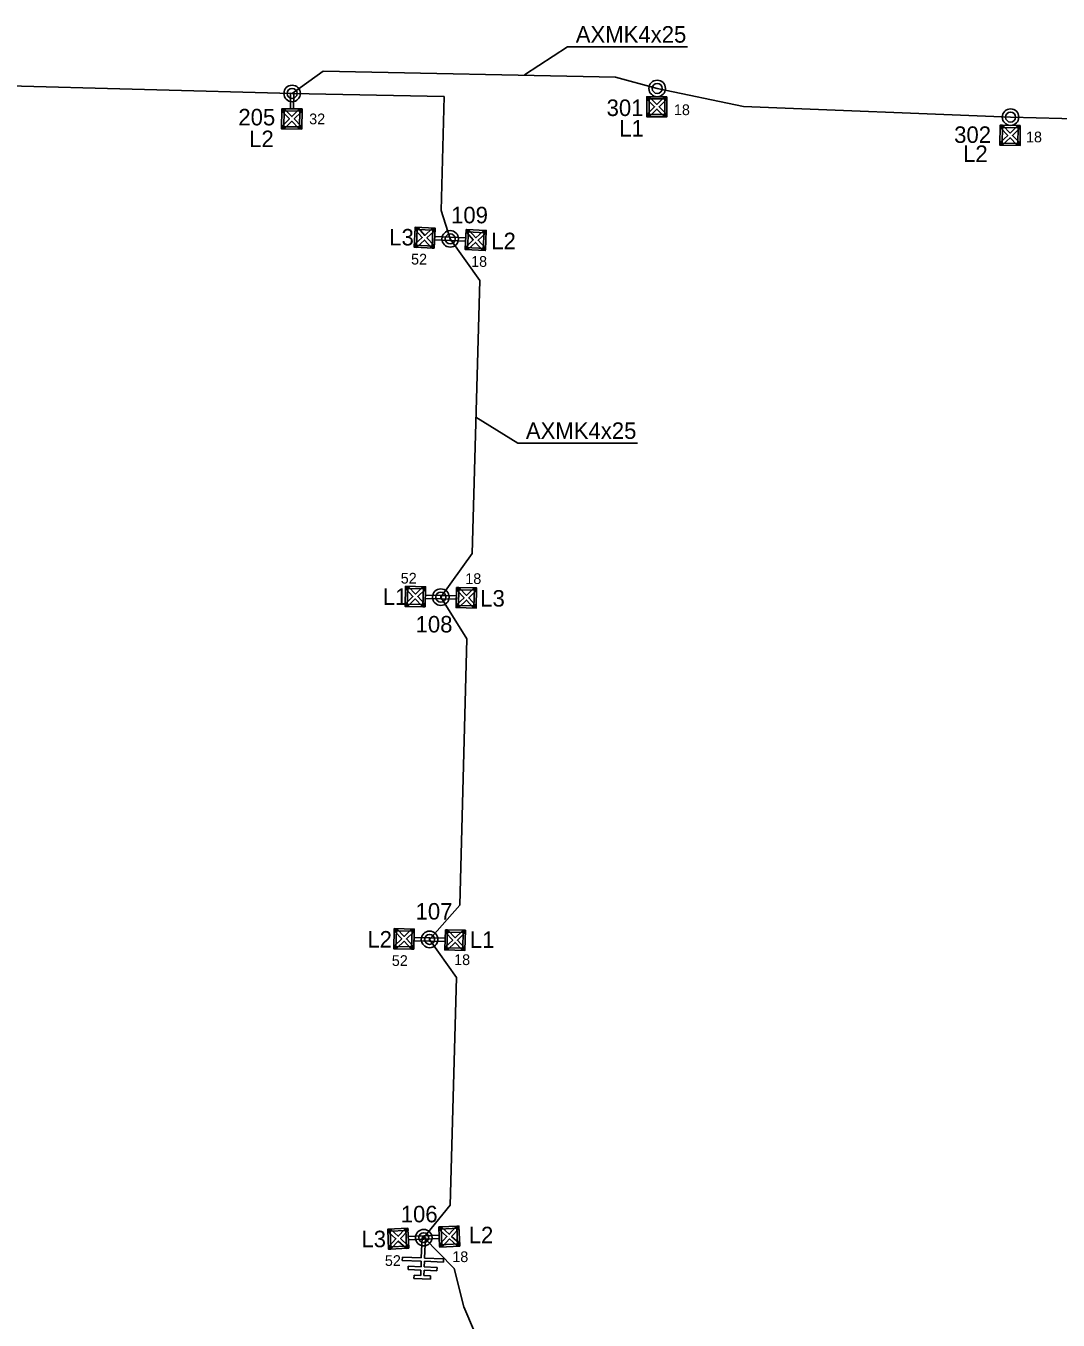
# Model space of a CAD drawing. Extents: x 25497852 to 25498297, y 6686544 to 6687252.
# Drawn here: x 25498074.6 to 25498168.3, y 6687062.7 to 6687180.2 of the extents above; entities that cross this region are included whole.
import ezdxf

# ---------------------------------------------------------------- set-up
doc = ezdxf.new("R2010")
doc.units = 0
for name, color, linetype in [('KayttoOikeusYksikko_piste_tunnus', 7, 'Continuous'), ('KiinteistoNimi', 7, 'Continuous'), ('Rajamerkki_tonttipyykki', 7, 'Continuous'), ('Rasitealue', 7, 'Continuous'), ('Rasiteviiva', 7, 'Continuous'), ('Taso 1', 7, 'Continuous')]:
    doc.layers.add(name, color=color, linetype=linetype)

msp = doc.modelspace()

# ---------------------------------------------------------------- linework, layer by layer
at = {"layer": 'KayttoOikeusYksikko_piste_tunnus'}
for points in [[(25498098.89, 6687174.02), (25498098.88, 6687172.62), (25498098.58, 6687172.62), (25498098.59, 6687174.03)], [(25498131.14, 6687173.72), (25498131.14, 6687171.9), (25498130.94, 6687171.9), (25498130.94, 6687173.72)], [(25498132.76, 6687173.72), (25498132.76, 6687173.52), (25498131, 6687173.52), (25498131, 6687173.72)], [(25498131.21, 6687173.66), (25498131.85, 6687173.02), (25498132.49, 6687173.66), (25498132.7, 6687173.66), (25498132.7, 6687173.45), (25498132.06, 6687172.81), (25498132.7, 6687172.17), (25498132.7, 6687171.96), (25498132.49, 6687171.96), (25498131.85, 6687172.6), (25498131.21, 6687171.96), (25498131, 6687171.96), (25498131, 6687172.17), (25498131.64, 6687172.81), (25498131, 6687173.45), (25498131, 6687173.66)], [(25498132.76, 6687171.96), (25498132.76, 6687173.66), (25498132.56, 6687173.66), (25498132.56, 6687171.96)], [(25498098.01, 6687172.63), (25498097.99, 6687170.8), (25498097.79, 6687170.8), (25498097.81, 6687172.63)], [(25498098.09, 6687172.56), (25498098.72, 6687171.92), (25498099.36, 6687172.55), (25498099.58, 6687172.55), (25498099.57, 6687172.33), (25498098.93, 6687171.7), (25498099.56, 6687171.06), (25498099.56, 6687170.85), (25498099.35, 6687170.85), (25498098.71, 6687171.49), (25498098.07, 6687170.86), (25498097.85, 6687170.87), (25498097.86, 6687171.08), (25498098.5, 6687171.71), (25498097.87, 6687172.35), (25498097.87, 6687172.57)], [(25498099.64, 6687172.61), (25498099.64, 6687172.41), (25498097.87, 6687172.43), (25498097.87, 6687172.63)], [(25498099.62, 6687170.85), (25498099.64, 6687172.55), (25498099.44, 6687172.55), (25498099.42, 6687170.85)], [(25498097.86, 6687171), (25498097.85, 6687170.8), (25498099.62, 6687170.78), (25498099.62, 6687170.98)], [(25498131, 6687172.1), (25498131, 6687171.9), (25498132.76, 6687171.9), (25498132.76, 6687172.1)], [(25498163.22, 6687171.13), (25498163.19, 6687169.31), (25498162.99, 6687169.31), (25498163.02, 6687171.14)], [(25498163.29, 6687171.07), (25498163.92, 6687170.42), (25498164.57, 6687171.05), (25498164.78, 6687171.05), (25498164.78, 6687170.84), (25498164.13, 6687170.21), (25498164.76, 6687169.56), (25498164.76, 6687169.35), (25498164.54, 6687169.35), (25498163.91, 6687170), (25498163.27, 6687169.37), (25498163.05, 6687169.37), (25498163.06, 6687169.59), (25498163.71, 6687170.21), (25498163.08, 6687170.86), (25498163.08, 6687171.07)], [(25498164.84, 6687171.11), (25498164.84, 6687170.91), (25498163.08, 6687170.94), (25498163.08, 6687171.14)], [(25498164.82, 6687169.35), (25498164.84, 6687171.05), (25498164.64, 6687171.05), (25498164.62, 6687169.35)], [(25498163.06, 6687169.51), (25498163.05, 6687169.31), (25498164.82, 6687169.29), (25498164.82, 6687169.49)], [(25498110.1, 6687161.81), (25498109.9, 6687161.82), (25498109.82, 6687160.06), (25498110.02, 6687160.05)], [(25498111.65, 6687161.53), (25498110.98, 6687160.92), (25498111.59, 6687160.25), (25498111.58, 6687160.04), (25498111.37, 6687160.05), (25498110.76, 6687160.71), (25498110.09, 6687160.11), (25498109.88, 6687160.12), (25498109.89, 6687160.33), (25498110.56, 6687160.94), (25498109.95, 6687161.61), (25498109.96, 6687161.82), (25498110.17, 6687161.81), (25498110.78, 6687161.14), (25498111.45, 6687161.75), (25498111.66, 6687161.74)], [(25498111.72, 6687161.6), (25498109.9, 6687161.68), (25498109.9, 6687161.88), (25498111.73, 6687161.79)], [(25498111.64, 6687159.97), (25498111.44, 6687159.98), (25498111.52, 6687161.74), (25498111.72, 6687161.73)], [(25498114.54, 6687161.66), (25498114.74, 6687161.65), (25498114.65, 6687159.89), (25498114.45, 6687159.9)], [(25498114.53, 6687160.11), (25498115.19, 6687160.72), (25498114.59, 6687161.39), (25498114.6, 6687161.6), (25498114.81, 6687161.59), (25498115.41, 6687160.92), (25498116.08, 6687161.53), (25498116.29, 6687161.52), (25498116.28, 6687161.31), (25498115.62, 6687160.7), (25498116.22, 6687160.03), (25498116.21, 6687159.82), (25498116, 6687159.83), (25498115.39, 6687160.49), (25498114.73, 6687159.89), (25498114.52, 6687159.9)], [(25498116.3, 6687161.58), (25498114.6, 6687161.66), (25498114.59, 6687161.46), (25498116.29, 6687161.38)], [(25498116.08, 6687159.82), (25498116.28, 6687159.81), (25498116.36, 6687161.58), (25498116.16, 6687161.59)], [(25498113.08, 6687160.67), (25498111.68, 6687160.73), (25498111.69, 6687161.03), (25498113.1, 6687160.97)], [(25498113.1, 6687160.97), (25498114.5, 6687160.9), (25498114.49, 6687160.6), (25498113.08, 6687160.67)], [(25498109.88, 6687160.06), (25498111.58, 6687159.98), (25498111.59, 6687160.17), (25498109.89, 6687160.25)], [(25498114.46, 6687160.04), (25498116.28, 6687159.95), (25498116.27, 6687159.75), (25498114.45, 6687159.84)], [(25498109.23, 6687129.22), (25498109.03, 6687129.23), (25498108.99, 6687127.46), (25498109.19, 6687127.46)], [(25498110.85, 6687129.04), (25498109.03, 6687129.09), (25498109.04, 6687129.29), (25498110.86, 6687129.24)], [(25498110.79, 6687128.97), (25498110.14, 6687128.35), (25498110.76, 6687127.69), (25498110.75, 6687127.48), (25498110.54, 6687127.49), (25498109.92, 6687128.14), (25498109.27, 6687127.52), (25498109.05, 6687127.52), (25498109.06, 6687127.73), (25498109.71, 6687128.36), (25498109.09, 6687129.01), (25498109.1, 6687129.22), (25498109.31, 6687129.22), (25498109.93, 6687128.57), (25498110.58, 6687129.19), (25498110.8, 6687129.18)], [(25498110.81, 6687127.42), (25498110.61, 6687127.42), (25498110.66, 6687129.19), (25498110.86, 6687129.18)], [(25498113.67, 6687129.17), (25498113.87, 6687129.17), (25498113.83, 6687127.4), (25498113.63, 6687127.41)], [(25498113.7, 6687127.62), (25498114.35, 6687128.24), (25498113.73, 6687128.9), (25498113.73, 6687129.11), (25498113.94, 6687129.1), (25498114.57, 6687128.45), (25498115.22, 6687129.07), (25498115.43, 6687129.07), (25498115.43, 6687128.86), (25498114.77, 6687128.23), (25498115.4, 6687127.58), (25498115.39, 6687127.37), (25498115.18, 6687127.37), (25498114.56, 6687128.03), (25498113.9, 6687127.4), (25498113.69, 6687127.41)], [(25498115.43, 6687129.13), (25498113.73, 6687129.17), (25498113.73, 6687128.97), (25498115.43, 6687128.93)], [(25498115.25, 6687127.37), (25498115.45, 6687127.36), (25498115.49, 6687129.13), (25498115.29, 6687129.13)], [(25498109.05, 6687127.46), (25498110.75, 6687127.42), (25498110.76, 6687127.62), (25498109.06, 6687127.66)], [(25498112.24, 6687128.15), (25498110.83, 6687128.18), (25498110.84, 6687128.48), (25498112.25, 6687128.45)], [(25498112.25, 6687128.45), (25498113.65, 6687128.41), (25498113.65, 6687128.11), (25498112.24, 6687128.15)], [(25498113.63, 6687127.55), (25498115.46, 6687127.5), (25498115.45, 6687127.3), (25498113.63, 6687127.35)], [(25498108.21, 6687098.15), (25498108.01, 6687098.16), (25498107.97, 6687096.39), (25498108.17, 6687096.39)], [(25498109.83, 6687097.97), (25498108.01, 6687098.02), (25498108.01, 6687098.22), (25498109.83, 6687098.17)], [(25498109.77, 6687097.9), (25498109.11, 6687097.28), (25498109.73, 6687096.62), (25498109.73, 6687096.41), (25498109.52, 6687096.42), (25498108.9, 6687097.07), (25498108.24, 6687096.45), (25498108.03, 6687096.45), (25498108.03, 6687096.66), (25498108.69, 6687097.29), (25498108.07, 6687097.94), (25498108.07, 6687098.16), (25498108.28, 6687098.15), (25498108.91, 6687097.5), (25498109.56, 6687098.12), (25498109.77, 6687098.11)], [(25498109.79, 6687096.35), (25498109.59, 6687096.35), (25498109.63, 6687098.12), (25498109.83, 6687098.11)], [(25498111.21, 6687097.08), (25498109.81, 6687097.11), (25498109.82, 6687097.41), (25498111.22, 6687097.38)], [(25498111.22, 6687097.38), (25498112.63, 6687097.34), (25498112.62, 6687097.04), (25498111.21, 6687097.08)], [(25498112.65, 6687098.1), (25498112.85, 6687098.1), (25498112.8, 6687096.33), (25498112.6, 6687096.34)], [(25498112.67, 6687096.55), (25498113.32, 6687097.17), (25498112.7, 6687097.83), (25498112.71, 6687098.04), (25498112.92, 6687098.03), (25498113.54, 6687097.38), (25498114.2, 6687098), (25498114.41, 6687098), (25498114.4, 6687097.79), (25498113.75, 6687097.16), (25498114.37, 6687096.51), (25498114.37, 6687096.3), (25498114.15, 6687096.3), (25498113.53, 6687096.96), (25498112.88, 6687096.33), (25498112.67, 6687096.34)], [(25498114.41, 6687098.06), (25498112.71, 6687098.1), (25498112.7, 6687097.9), (25498114.4, 6687097.86)], [(25498114.23, 6687096.3), (25498114.43, 6687096.29), (25498114.47, 6687098.06), (25498114.27, 6687098.06)], [(25498108.03, 6687096.39), (25498109.73, 6687096.35), (25498109.73, 6687096.55), (25498108.03, 6687096.59)], [(25498112.61, 6687096.48), (25498114.43, 6687096.43), (25498114.43, 6687096.23), (25498112.6, 6687096.28)], [(25498112.06, 6687071.13), (25498112.26, 6687071.14), (25498112.33, 6687069.38), (25498112.13, 6687069.37)], [(25498113.82, 6687071.21), (25498112.12, 6687071.14), (25498112.13, 6687070.94), (25498113.83, 6687071.01)], [(25498112.19, 6687069.59), (25498112.8, 6687070.25), (25498112.13, 6687070.86), (25498112.12, 6687071.08), (25498112.33, 6687071.09), (25498113, 6687070.47), (25498113.61, 6687071.14), (25498113.82, 6687071.15), (25498113.83, 6687070.94), (25498113.22, 6687070.27), (25498113.89, 6687069.66), (25498113.9, 6687069.45), (25498113.68, 6687069.44), (25498113.02, 6687070.05), (25498112.41, 6687069.38), (25498112.2, 6687069.37)], [(25498113.76, 6687069.44), (25498113.96, 6687069.45), (25498113.88, 6687071.21), (25498113.68, 6687071.2)], [(25498109.26, 6687070.82), (25498107.43, 6687070.74), (25498107.43, 6687070.94), (25498109.25, 6687071.01)], [(25498107.63, 6687070.88), (25498107.43, 6687070.88), (25498107.5, 6687069.11), (25498107.7, 6687069.12)], [(25498109.2, 6687070.74), (25498108.59, 6687070.07), (25498109.25, 6687069.46), (25498109.26, 6687069.25), (25498109.05, 6687069.24), (25498108.38, 6687069.85), (25498107.77, 6687069.19), (25498107.56, 6687069.18), (25498107.55, 6687069.39), (25498108.16, 6687070.06), (25498107.5, 6687070.67), (25498107.49, 6687070.88), (25498107.7, 6687070.89), (25498108.37, 6687070.28), (25498108.98, 6687070.94), (25498109.19, 6687070.95)], [(25498109.33, 6687069.19), (25498109.13, 6687069.18), (25498109.05, 6687070.95), (25498109.25, 6687070.95)], [(25498110.7, 6687070.01), (25498109.29, 6687069.95), (25498109.28, 6687070.25), (25498110.69, 6687070.31)], [(25498110.69, 6687070.31), (25498112.09, 6687070.37), (25498112.1, 6687070.07), (25498110.7, 6687070.01)], [(25498107.57, 6687069.12), (25498109.26, 6687069.19), (25498109.26, 6687069.39), (25498107.56, 6687069.32)], [(25498112.13, 6687069.51), (25498113.95, 6687069.59), (25498113.96, 6687069.39), (25498112.14, 6687069.31)]]:
    msp.add_lwpolyline(points, close=True, dxfattribs=at)
at = {"layer": 'KiinteistoNimi'}
for centre, radius in [((25498098.74, 6687174.02), 0.75), ((25498131.88, 6687174.47), 0.75), ((25498131.88, 6687174.47), 0.45), ((25498098.74, 6687174.02), 0.45), ((25498163.96, 6687171.87), 0.75), ((25498163.96, 6687171.87), 0.45), ((25498113.09, 6687160.82), 0.75), ((25498113.09, 6687160.82), 0.45), ((25498112.24, 6687128.3), 0.75), ((25498112.24, 6687128.3), 0.45), ((25498111.22, 6687097.23), 0.75), ((25498111.22, 6687097.23), 0.45), ((25498110.69, 6687070.16), 0.75), ((25498110.69, 6687070.16), 0.45)]:
    msp.add_circle(centre, radius, dxfattribs=at)
at = {"layer": 'Rajamerkki_tonttipyykki'}
for p, q in [((25498110.47, 6687068.32), (25498110.54, 6687070.17)), ((25498110.54, 6687070.17), (25498110.84, 6687070.16)), ((25498110.84, 6687070.16), (25498110.77, 6687068.31)), ((25498108.73, 6687068.09), (25498108.75, 6687068.39)), ((25498110.46, 6687068.02), (25498108.73, 6687068.09)), ((25498108.75, 6687068.39), (25498110.47, 6687068.32)), ((25498110.44, 6687067.52), (25498110.46, 6687068.02)), ((25498110.76, 6687068.01), (25498110.74, 6687067.51)), ((25498112.48, 6687067.94), (25498110.76, 6687068.01)), ((25498110.77, 6687068.31), (25498112.49, 6687068.24)), ((25498112.49, 6687068.24), (25498112.48, 6687067.94)), ((25498109.27, 6687067.27), (25498109.28, 6687067.57)), ((25498110.43, 6687067.22), (25498109.27, 6687067.27)), ((25498109.28, 6687067.57), (25498110.44, 6687067.52)), ((25498109.8, 6687066.45), (25498109.81, 6687066.75)), ((25498111.3, 6687066.39), (25498109.8, 6687066.45)), ((25498109.81, 6687066.75), (25498110.41, 6687066.72)), ((25498110.41, 6687066.72), (25498110.43, 6687067.22)), ((25498110.73, 6687067.21), (25498110.71, 6687066.71)), ((25498110.71, 6687066.71), (25498111.31, 6687066.69)), ((25498111.89, 6687067.16), (25498110.73, 6687067.21)), ((25498110.74, 6687067.51), (25498111.9, 6687067.46)), ((25498111.31, 6687066.69), (25498111.3, 6687066.39)), ((25498111.9, 6687067.46), (25498111.89, 6687067.16))]:
    msp.add_line(p, q, dxfattribs=at)
at = {"layer": 'Rasitealue'}
for p, q in [((25498065.63, 6687174.9), (25498098.74, 6687174.02)), ((25498163.96, 6687171.87), (25498195.63, 6687171.09))]:
    msp.add_line(p, q, dxfattribs=at)
for points in [[(25498098.74, 6687174.02), (25498101.56, 6687176.05), (25498128.1, 6687175.5), (25498131.88, 6687174.47)], [(25498113.09, 6687160.82), (25498112.26, 6687163.39), (25498112.54, 6687173.74), (25498098.74, 6687174.02)], [(25498131.88, 6687174.47), (25498139.73, 6687172.83), (25498163.96, 6687171.87)], [(25498112.24, 6687128.3), (25498115.07, 6687132.27), (25498115.78, 6687157.03), (25498113.09, 6687160.82)], [(25498111.22, 6687097.23), (25498113.96, 6687100.34), (25498114.59, 6687124.51), (25498112.24, 6687128.3)], [(25498110.69, 6687070.16), (25498113.08, 6687073.12), (25498113.67, 6687093.76), (25498111.22, 6687097.23)], [(25498120.77, 6687050.75), (25498119.4, 6687055), (25498116.27, 6687059.35), (25498114.33, 6687063.87), (25498113.44, 6687067.35), (25498110.69, 6687070.16)]]:
    msp.add_lwpolyline(points, dxfattribs=at)
at = {"layer": 'Taso 1'}
for points in [[(25498134.62, 6687178.24), (25498123.75, 6687178.24), (25498119.84, 6687175.71)], [(25498130.09, 6687142.27), (25498119.23, 6687142.27), (25498115.42, 6687144.65)]]:
    msp.add_lwpolyline(points, dxfattribs=at)

# ---------------------------------------------------------------- texts
at = {"layer": 'Rasiteviiva'}
for s, height, p in [('AXMK4x25', 1.5, (25498124.49, 6687178.63)), ('301', 1.5, (25498127.29, 6687171.97)), ('205', 1.5, (25498093.86, 6687171.12)), ('32', 0.975, (25498100.29, 6687171.22)), ('18', 0.975, (25498133.4, 6687172.05)), ('L1', 1.5, (25498128.44, 6687170.11)), ('302', 1.5, (25498158.84, 6687169.53)), ('L2', 1.5, (25498094.84, 6687169.15)), ('18', 0.975, (25498165.36, 6687169.58)), ('L2', 1.5, (25498159.65, 6687167.8)), ('109', 1.5, (25498113.17, 6687162.23)), ('L3', 1.5, (25498107.56, 6687160.22)), ('L2', 1.5, (25498116.82, 6687159.88)), ('52', 0.975, (25498109.54, 6687158.49)), ('18', 0.975, (25498114.99, 6687158.28)), ('AXMK4x25', 1.5, (25498119.96, 6687142.66)), ('52', 0.975, (25498108.6, 6687129.53)), ('18', 0.975, (25498114.46, 6687129.49)), ('L1', 1.5, (25498106.97, 6687127.59)), ('L3', 1.5, (25498115.82, 6687127.44)), ('108', 1.5, (25498109.95, 6687125.09)), ('107', 1.5, (25498109.95, 6687099.03)), ('L2', 1.5, (25498105.57, 6687096.49)), ('L1', 1.5, (25498114.88, 6687096.46)), ('52', 0.975, (25498107.79, 6687094.82)), ('18', 0.975, (25498113.45, 6687094.9)), ('106', 1.5, (25498108.6, 6687071.55)), ('L2', 1.5, (25498114.77, 6687069.65)), ('L3', 1.5, (25498105.03, 6687069.29)), ('18', 0.975, (25498113.28, 6687067.94)), ('52', 0.975, (25498107.16, 6687067.59))]:
    msp.add_text(s, height=height, dxfattribs=at).set_placement(p)

doc.saveas('drawing.dxf')
